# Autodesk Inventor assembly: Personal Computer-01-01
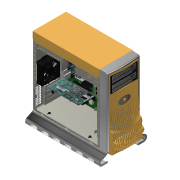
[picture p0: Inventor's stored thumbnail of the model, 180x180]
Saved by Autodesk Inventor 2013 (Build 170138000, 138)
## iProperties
Company: Autodesk Inc.
Created: 2006-09
Part Number: Personal Computer-01-01
Document SubType Name: Assembly
Designer: Autodesk Inc.
Mass: 5059.49 g
Surface Area: 31504.8 cm^2
Volume: 5059.49 cm^3
Density: 1 g/cm^3
Title: Personal Computer
Author: Autodesk Inc.
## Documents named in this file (10)
- Z:\_DATEN\Personal Computer\Personal Computer.iam
- Z:\_DATEN\Personal Computer\PC Chassis\PC Chassis.iam
- Z:\_DATEN\Personal Computer\Motherboard\Motherboard.iam
- Z:\_DATEN\Personal Computer\Graphics Card\Graphics Card.iam
- Z:\_DATEN\Personal Computer\Power Supply\Power Supply.iam
- Z:\_DATEN\Personal Computer\Drives\CDROM.ipt
- Z:\_DATEN\Personal Computer\Drives\Hard Drive.ipt
- Z:\_DATEN\Personal Computer\PC Cover\Inventor PC Cover\Case Top.ipt
- Z:\_DATEN\Personal Computer\PC Cover\Inventor PC Cover\Stylistic Front Face.ipt
- Z:\_DATEN\Personal Computer\PC Cover\Inventor PC Cover\LED Button.ipt
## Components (11 placed, 9 different names)
1. PC Chassis:1 [sub-assembly] — Mate:1, Mate:3, Mate:7, Mate:8, Mate:9, Mate:10, Mate:11, Angle:1, Mate:12, Mate:13, Angle:2, Mate:14, Mate:15, Angle:3, Mate:16, Mate:17, Angle:4, Mate:79, Mate:80, Mate:81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
2. Case Top:1 — Mate:79, Mate:80, Mate:81, Mate:82, Flush:5
3. Stylistic Front Face:1 — Mate:82, Flush:5, Mate:83, Mate:85, Mate:86
4. LED Button:1 — Mate:84, Mate:85, Mate:86
5. Power Supply:1 [sub-assembly] — Mate:7, Mate:8, Mate:9
6. Motherboard:1 [sub-assembly] — Mate:5, Mate:6
7. Graphics Card:1 [sub-assembly] — Mate:1, Mate:3, Mate:5, Mate:6
8. CDROM:1 — Mate:10, Mate:11, Angle:1
9. CDROM:2 — Mate:12, Mate:13, Angle:2
10. Hard Drive:1 — Mate:16, Mate:17, Angle:4
11. Hard Drive:2 — Mate:14, Mate:15, Angle:3
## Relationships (28: Mate 23, Angle 4, Flush 1)
- Mate:1: PC Chassis:1 ↔ Graphics Card:1
- Mate:3: PC Chassis:1 ↔ Graphics Card:1
- Mate:5: Motherboard:1 ↔ Graphics Card:1
- Mate:6: Motherboard:1 ↔ Graphics Card:1
- Mate:7: PC Chassis:1 ↔ Power Supply:1
- Mate:8: PC Chassis:1 ↔ Power Supply:1
- Mate:9: PC Chassis:1 ↔ Power Supply:1
- Mate:10: PC Chassis:1 ↔ CDROM:1
- Mate:11: PC Chassis:1 ↔ CDROM:1
- Angle:1: PC Chassis:1 ↔ CDROM:1
- Mate:12: PC Chassis:1 ↔ CDROM:2
- Mate:13: PC Chassis:1 ↔ CDROM:2
- Angle:2: PC Chassis:1 ↔ CDROM:2
- Mate:14: PC Chassis:1 ↔ Hard Drive:2
- Mate:15: PC Chassis:1 ↔ Hard Drive:2
- Angle:3: PC Chassis:1 ↔ Hard Drive:2
- Mate:16: PC Chassis:1 ↔ Hard Drive:1
- Mate:17: PC Chassis:1 ↔ Hard Drive:1
- Angle:4: PC Chassis:1 ↔ Hard Drive:1
- Mate:79: PC Chassis:1 ↔ Case Top:1
- Mate:80: PC Chassis:1 ↔ Case Top:1
- Mate:81: PC Chassis:1 ↔ Case Top:1
- Mate:82: Case Top:1 ↔ Stylistic Front Face:1
- Flush:5: Case Top:1 ↔ Stylistic Front Face:1
- Mate:83: PC Chassis:1 ↔ Stylistic Front Face:1
- Mate:84: PC Chassis:1 ↔ LED Button:1
- Mate:85: Stylistic Front Face:1 ↔ LED Button:1
- Mate:86: Stylistic Front Face:1 ↔ LED Button:1
